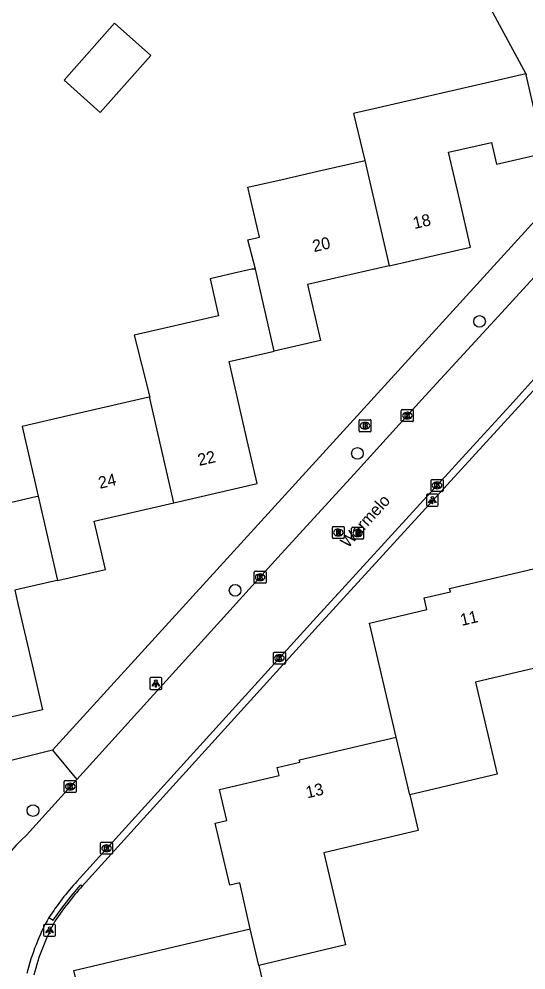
# Model space of a CAD drawing. Extents: x 157663 to 158496, y 379212 to 380934.
# Drawn here: x 158156.2 to 158198.6, y 380518.3 to 380597.8 of the extents above; entities that cross this region are included whole.
import ezdxf

# ---------------------------------------------------------------- set-up
doc = ezdxf.new("R2010")
doc.units = 0
for name, color, linetype in [('IMGEO_Boom', 7, 'Continuous'), ('IMGEO_Brandkraan', 7, 'Continuous'), ('IMGEO_Groenvoorziening', 7, 'Continuous'), ('IMGEO_Kolk', 7, 'Continuous'), ('IMGEO_Lichtpunt', 7, 'Continuous'), ('IMGEO_Openbare_ruimte_label', 7, 'Continuous'), ('IMGEO_Pand', 7, 'Continuous'), ('IMGEO_Pand_nummerreeks', 7, 'Continuous'), ('IMGEO_Rijbaan_lokaal_open', 7, 'Continuous'), ('IMGEO_Rioolput', 7, 'Continuous'), ('IMGEO_Voetpad_open', 7, 'Continuous')]:
    doc.layers.add(name, color=color, linetype=linetype)

msp = doc.modelspace()

# ---------------------------------------------------------------- linework, layer by layer
at = {"layer": 'IMGEO_Boom'}
for centre in [(158194.698, 380572.534), (158184.483, 380561.502), (158174.25, 380550.048), (158157.337, 380531.639)]:
    msp.add_circle(centre, 0.489, dxfattribs=at)
at = {"layer": 'IMGEO_Brandkraan'}
for p, q in [((158184.616, 380563.393), (158184.616, 380564.245)), ((158184.691, 380564.319), (158185.543, 380564.319)), ((158185.104, 380564.099), (158185.129, 380564.099)), ((158185.617, 380564.245), (158185.617, 380563.393)), ((158185.543, 380563.319), (158184.691, 380563.319)), ((158185.127, 380563.539), (158185.102, 380563.539))]:
    msp.add_line(p, q, dxfattribs=at)
for points in [[(158184.616, 380563.393), (158184.616, 380564.245)], [(158184.691, 380564.319), (158185.543, 380564.319)], [(158184.964, 380564.019), (158184.964, 380563.619), (158185.177, 380563.619)], [(158185.195, 380564.019), (158184.964, 380564.019)], [(158185.143, 380563.938), (158185.089, 380563.938), (158185.089, 380563.862)], [(158185.089, 380563.862), (158185.142, 380563.862)], [(158185.151, 380563.786), (158185.089, 380563.786), (158185.089, 380563.705)], [(158185.089, 380563.705), (158185.151, 380563.705)], [(158185.617, 380564.245), (158185.617, 380563.393)], [(158185.543, 380563.319), (158184.691, 380563.319)]]:
    msp.add_lwpolyline(points, dxfattribs=at)
for centre, radius, start, end in [((158184.693, 380564.243), 0.0765, 91.55205, 178.44795), ((158184.693, 380564.243), 0.0765, 91.55205, 178.44795), ((158185.144, 380563.9), 0.0379, 267.82845, 90.93552), ((158185.152, 380563.745), 0.0404, 269.87594, 90.50774), ((158185.183, 380563.87), 0.251, 268.66757, 293.53466), ((158185.199, 380563.874), 0.145, 59.4692, 91.53667), ((158185.224, 380563.921), 0.0922, 285.51372, 58.15012), ((158185.229, 380563.729), 0.105, 301.31148, 78.98903), ((158185.541, 380564.243), 0.0765, 1.55205, 88.44795), ((158185.541, 380564.243), 0.0765, 1.55205, 88.44795), ((158184.693, 380563.395), 0.0765, 181.55205, 268.44795), ((158184.693, 380563.395), 0.0765, 181.55205, 268.44795), ((158185.541, 380563.395), 0.0765, 271.55205, 358.44795), ((158185.541, 380563.395), 0.0765, 271.55205, 358.44795)]:
    msp.add_arc(centre, radius, start, end, dxfattribs=at)
for centre, major_axis, ratio, start_param, end_param in [((158185.103, 380563.819), (-0.387, 0.002), 0.722429, 4.712389, 7.853982), ((158185.128, 380563.819), (-0.39, 0.002), 0.717154, 1.570796, 4.712389)]:
    msp.add_ellipse(centre, major_axis=major_axis, ratio=ratio, start_param=start_param, end_param=end_param, dxfattribs=at)
at = {"layer": 'IMGEO_Groenvoorziening'}
msp.add_lwpolyline([(158173.501, 380635.134), (158174.629, 380630.369), (158177.674, 380619.056), (158182.988, 380612.841), (158191.552, 380606.256), (158198.57, 380593.237)], dxfattribs=at)
at = {"layer": 'IMGEO_Kolk'}
for p, q in [((158188.155, 380564.235), (158188.155, 380565.087)), ((158188.23, 380565.161), (158189.082, 380565.161)), ((158188.643, 380564.941), (158188.668, 380564.941)), ((158189.156, 380565.087), (158189.156, 380564.235)), ((158189.082, 380564.161), (158188.23, 380564.161)), ((158188.666, 380564.381), (158188.641, 380564.381)), ((158190.647, 380558.4), (158190.647, 380559.252)), ((158190.722, 380559.326), (158191.574, 380559.326)), ((158191.135, 380559.106), (158191.16, 380559.106)), ((158191.648, 380559.252), (158191.648, 380558.4)), ((158191.574, 380558.326), (158190.722, 380558.326)), ((158191.158, 380558.546), (158191.133, 380558.546)), ((158175.84, 380550.718), (158175.84, 380551.57)), ((158175.915, 380551.644), (158176.767, 380551.644)), ((158176.328, 380551.424), (158176.353, 380551.424)), ((158176.841, 380551.57), (158176.841, 380550.718)), ((158176.767, 380550.644), (158175.915, 380550.644)), ((158176.351, 380550.864), (158176.326, 380550.864)), ((158177.451, 380543.961), (158177.451, 380544.813)), ((158177.526, 380544.887), (158178.378, 380544.887)), ((158177.939, 380544.667), (158177.964, 380544.667)), ((158178.452, 380544.813), (158178.452, 380543.961)), ((158178.378, 380543.887), (158177.526, 380543.887)), ((158177.962, 380544.107), (158177.937, 380544.107)), ((158159.952, 380533.215), (158159.952, 380534.067)), ((158160.027, 380534.141), (158160.879, 380534.141)), ((158160.44, 380533.921), (158160.465, 380533.921)), ((158160.953, 380534.067), (158160.953, 380533.215)), ((158160.879, 380533.141), (158160.027, 380533.141)), ((158160.463, 380533.361), (158160.438, 380533.361)), ((158162.993, 380528.058), (158162.993, 380528.91)), ((158163.068, 380528.984), (158163.92, 380528.984)), ((158163.481, 380528.764), (158163.506, 380528.764)), ((158163.994, 380528.91), (158163.994, 380528.058)), ((158163.92, 380527.984), (158163.068, 380527.984)), ((158163.504, 380528.204), (158163.479, 380528.204))]:
    msp.add_line(p, q, dxfattribs=at)
for points in [[(158188.155, 380564.235), (158188.155, 380565.087)], [(158188.23, 380565.161), (158189.082, 380565.161)], [(158188.476, 380564.861), (158188.599, 380564.861), (158188.599, 380564.71), (158188.729, 380564.861), (158188.893, 380564.861), (158188.747, 380564.71), (158188.9, 380564.461), (158188.748, 380564.461), (158188.663, 380564.625), (158188.599, 380564.558), (158188.599, 380564.461), (158188.476, 380564.461), (158188.476, 380564.861)], [(158189.156, 380565.087), (158189.156, 380564.235)], [(158189.082, 380564.161), (158188.23, 380564.161)], [(158190.647, 380558.4), (158190.647, 380559.252)], [(158190.722, 380559.326), (158191.574, 380559.326)], [(158190.968, 380559.026), (158191.091, 380559.026), (158191.091, 380558.875), (158191.221, 380559.026), (158191.385, 380559.026), (158191.239, 380558.875), (158191.392, 380558.626), (158191.24, 380558.626), (158191.155, 380558.79), (158191.091, 380558.723), (158191.091, 380558.626), (158190.968, 380558.626), (158190.968, 380559.026)], [(158191.648, 380559.252), (158191.648, 380558.4)], [(158191.574, 380558.326), (158190.722, 380558.326)], [(158175.84, 380550.718), (158175.84, 380551.57)], [(158175.915, 380551.644), (158176.767, 380551.644)], [(158176.161, 380551.344), (158176.284, 380551.344), (158176.284, 380551.193), (158176.414, 380551.344), (158176.578, 380551.344), (158176.432, 380551.193), (158176.585, 380550.944), (158176.433, 380550.944), (158176.348, 380551.108), (158176.284, 380551.041), (158176.284, 380550.944), (158176.161, 380550.944), (158176.161, 380551.344)], [(158176.841, 380551.57), (158176.841, 380550.718)], [(158176.767, 380550.644), (158175.915, 380550.644)], [(158177.451, 380543.961), (158177.451, 380544.813)], [(158177.526, 380544.887), (158178.378, 380544.887)], [(158177.772, 380544.587), (158177.895, 380544.587), (158177.895, 380544.436), (158178.025, 380544.587), (158178.189, 380544.587), (158178.043, 380544.436), (158178.196, 380544.187), (158178.044, 380544.187), (158177.959, 380544.351), (158177.895, 380544.284), (158177.895, 380544.187), (158177.772, 380544.187), (158177.772, 380544.587)], [(158178.452, 380544.813), (158178.452, 380543.961)], [(158178.378, 380543.887), (158177.526, 380543.887)], [(158159.952, 380533.215), (158159.952, 380534.067)], [(158160.027, 380534.141), (158160.879, 380534.141)], [(158160.273, 380533.841), (158160.396, 380533.841), (158160.396, 380533.69), (158160.526, 380533.841), (158160.69, 380533.841), (158160.544, 380533.69), (158160.697, 380533.441), (158160.545, 380533.441), (158160.46, 380533.605), (158160.396, 380533.538), (158160.396, 380533.441), (158160.273, 380533.441), (158160.273, 380533.841)], [(158160.953, 380534.067), (158160.953, 380533.215)], [(158160.879, 380533.141), (158160.027, 380533.141)], [(158162.993, 380528.058), (158162.993, 380528.91)], [(158163.068, 380528.984), (158163.92, 380528.984)], [(158163.314, 380528.684), (158163.437, 380528.684), (158163.437, 380528.533), (158163.567, 380528.684), (158163.731, 380528.684), (158163.585, 380528.533), (158163.738, 380528.284), (158163.586, 380528.284), (158163.501, 380528.448), (158163.437, 380528.381), (158163.437, 380528.284), (158163.314, 380528.284), (158163.314, 380528.684)], [(158163.994, 380528.91), (158163.994, 380528.058)], [(158163.92, 380527.984), (158163.068, 380527.984)]]:
    msp.add_lwpolyline(points, dxfattribs=at)
for centre, start, end in [((158188.232, 380565.085), 91.55205, 178.44795), ((158188.232, 380565.085), 91.55205, 178.44795), ((158189.08, 380565.085), 1.55205, 88.44795), ((158189.08, 380565.085), 1.55205, 88.44795), ((158188.232, 380564.237), 181.55205, 268.44795), ((158188.232, 380564.237), 181.55205, 268.44795), ((158189.08, 380564.237), 271.55205, 358.44795), ((158189.08, 380564.237), 271.55205, 358.44795), ((158190.724, 380559.25), 91.55205, 178.44795), ((158190.724, 380559.25), 91.55205, 178.44795), ((158191.572, 380559.25), 1.55205, 88.44795), ((158191.572, 380559.25), 1.55205, 88.44795), ((158190.724, 380558.402), 181.55205, 268.44795), ((158190.724, 380558.402), 181.55205, 268.44795), ((158191.572, 380558.402), 271.55205, 358.44795), ((158191.572, 380558.402), 271.55205, 358.44795), ((158175.917, 380551.568), 91.55205, 178.44795), ((158175.917, 380551.568), 91.55205, 178.44795), ((158176.765, 380551.568), 1.55205, 88.44795), ((158176.765, 380551.568), 1.55205, 88.44795), ((158175.917, 380550.72), 181.55205, 268.44795), ((158175.917, 380550.72), 181.55205, 268.44795), ((158176.765, 380550.72), 271.55205, 358.44795), ((158176.765, 380550.72), 271.55205, 358.44795), ((158177.528, 380544.811), 91.55205, 178.44795), ((158177.528, 380544.811), 91.55205, 178.44795), ((158178.376, 380544.811), 1.55205, 88.44795), ((158178.376, 380544.811), 1.55205, 88.44795), ((158177.528, 380543.963), 181.55205, 268.44795), ((158177.528, 380543.963), 181.55205, 268.44795), ((158178.376, 380543.963), 271.55205, 358.44795), ((158178.376, 380543.963), 271.55205, 358.44795), ((158160.029, 380534.065), 91.55205, 178.44795), ((158160.029, 380534.065), 91.55205, 178.44795), ((158160.877, 380534.065), 1.55205, 88.44795), ((158160.877, 380534.065), 1.55205, 88.44795), ((158160.029, 380533.217), 181.55205, 268.44795), ((158160.029, 380533.217), 181.55205, 268.44795), ((158160.877, 380533.217), 271.55205, 358.44795), ((158160.877, 380533.217), 271.55205, 358.44795), ((158163.07, 380528.908), 91.55205, 178.44795), ((158163.07, 380528.908), 91.55205, 178.44795), ((158163.918, 380528.908), 1.55205, 88.44795), ((158163.918, 380528.908), 1.55205, 88.44795), ((158163.07, 380528.06), 181.55205, 268.44795), ((158163.07, 380528.06), 181.55205, 268.44795), ((158163.918, 380528.06), 271.55205, 358.44795), ((158163.918, 380528.06), 271.55205, 358.44795)]:
    msp.add_arc(centre, 0.0765, start, end, dxfattribs=at)
for centre, major_axis, ratio, start_param, end_param in [((158188.642, 380564.661), (-0.387, 0.002), 0.722429, 4.712389, 7.853982), ((158188.667, 380564.661), (-0.39, 0.002), 0.717154, 1.570796, 4.712389), ((158191.134, 380558.826), (-0.387, 0.002), 0.722429, 4.712389, 7.853982), ((158191.159, 380558.826), (-0.39, 0.002), 0.717154, 1.570796, 4.712389), ((158176.327, 380551.144), (-0.387, 0.002), 0.722429, 4.712389, 7.853982), ((158176.352, 380551.144), (-0.39, 0.002), 0.717154, 1.570796, 4.712389), ((158177.938, 380544.387), (-0.387, 0.002), 0.722429, 4.712389, 7.853982), ((158177.963, 380544.387), (-0.39, 0.002), 0.717154, 1.570796, 4.712389), ((158160.439, 380533.641), (-0.387, 0.002), 0.722429, 4.712389, 7.853982), ((158160.464, 380533.641), (-0.39, 0.002), 0.717154, 1.570796, 4.712389), ((158163.48, 380528.484), (-0.387, 0.002), 0.722429, 4.712389, 7.853982), ((158163.505, 380528.484), (-0.39, 0.002), 0.717154, 1.570796, 4.712389)]:
    msp.add_ellipse(centre, major_axis=major_axis, ratio=ratio, start_param=start_param, end_param=end_param, dxfattribs=at)
at = {"layer": 'IMGEO_Lichtpunt'}
for p, q in [((158191.154, 380558.089), (158190.346, 380558.089)), ((158191.154, 380558.089), (158190.346, 380558.089)), ((158190.252, 380557.994), (158190.252, 380557.187)), ((158190.252, 380557.994), (158190.252, 380557.187)), ((158191.248, 380557.187), (158191.248, 380557.994)), ((158191.248, 380557.187), (158191.248, 380557.994)), ((158190.346, 380557.093), (158191.154, 380557.093)), ((158190.346, 380557.093), (158191.154, 380557.093)), ((158167.115, 380542.671), (158167.115, 380541.864)), ((158167.115, 380542.671), (158167.115, 380541.864)), ((158168.017, 380542.766), (158167.209, 380542.766)), ((158168.017, 380542.766), (158167.209, 380542.766)), ((158168.111, 380541.864), (158168.111, 380542.671)), ((158168.111, 380541.864), (158168.111, 380542.671)), ((158167.209, 380541.77), (158168.017, 380541.77)), ((158167.209, 380541.77), (158168.017, 380541.77)), ((158158.223, 380522.027), (158158.223, 380521.22)), ((158158.223, 380522.027), (158158.223, 380521.22)), ((158159.125, 380522.122), (158158.317, 380522.122)), ((158159.125, 380522.122), (158158.317, 380522.122)), ((158159.219, 380521.22), (158159.219, 380522.027)), ((158159.219, 380521.22), (158159.219, 380522.027)), ((158158.317, 380521.126), (158159.125, 380521.126)), ((158158.317, 380521.126), (158159.125, 380521.126))]:
    msp.add_line(p, q, dxfattribs=at)
for points in [[(158190.626, 380557.658), (158190.665, 380557.63), (158190.477, 380557.368), (158190.439, 380557.395), (158190.626, 380557.658)], [(158190.728, 380557.61), (158190.775, 380557.61), (158190.775, 380557.288), (158190.728, 380557.288), (158190.728, 380557.61)], [(158190.838, 380557.63), (158190.876, 380557.657), (158191.063, 380557.395), (158191.024, 380557.367), (158190.838, 380557.63)], [(158167.489, 380542.335), (158167.528, 380542.307), (158167.34, 380542.045), (158167.302, 380542.072), (158167.489, 380542.335)], [(158167.591, 380542.287), (158167.638, 380542.287), (158167.638, 380541.965), (158167.591, 380541.965), (158167.591, 380542.287)], [(158167.701, 380542.307), (158167.739, 380542.334), (158167.926, 380542.072), (158167.887, 380542.044), (158167.701, 380542.307)], [(158158.597, 380521.691), (158158.636, 380521.663), (158158.448, 380521.401), (158158.41, 380521.428), (158158.597, 380521.691)], [(158158.699, 380521.643), (158158.746, 380521.643), (158158.746, 380521.321), (158158.699, 380521.321), (158158.699, 380521.643)], [(158158.809, 380521.663), (158158.847, 380521.69), (158159.034, 380521.428), (158158.995, 380521.4), (158158.809, 380521.663)]]:
    msp.add_lwpolyline(points, dxfattribs=at)
for centre in [(158190.751, 380557.792), (158167.614, 380542.469), (158158.722, 380521.825)]:
    msp.add_circle(centre, 0.0994, dxfattribs=at)
for centre, start, end in [((158190.346, 380557.994), 90, 180), ((158190.346, 380557.994), 90, 180), ((158191.154, 380557.994), 0, 90), ((158191.154, 380557.994), 0, 90), ((158190.346, 380557.187), 180, 270), ((158190.346, 380557.187), 180, 270), ((158191.154, 380557.187), 270, 0), ((158191.154, 380557.187), 270, 360), ((158167.209, 380542.671), 90, 180), ((158167.209, 380542.671), 90, 180), ((158168.017, 380542.671), 0, 90), ((158168.017, 380542.671), 0, 90), ((158167.209, 380541.864), 180, 270), ((158167.209, 380541.864), 180, 270), ((158168.017, 380541.864), 270, 0), ((158168.017, 380541.864), 270, 360), ((158158.317, 380522.027), 90, 180), ((158158.317, 380522.027), 90, 180), ((158159.125, 380522.027), 0, 90), ((158159.125, 380522.027), 0, 90), ((158158.317, 380521.22), 180, 270), ((158158.317, 380521.22), 180, 270), ((158159.125, 380521.22), 270, 0), ((158159.125, 380521.22), 270, 360)]:
    msp.add_arc(centre, 0.0946, start, end, dxfattribs=at)
at = {"layer": 'IMGEO_Pand'}
for points in [[(158162.964, 380590.019), (158159.934, 380592.701), (158164.152, 380597.466), (158167.182, 380594.783), (158162.964, 380590.019)], [(158198.57, 380593.237), (158194.846, 380592.382), (158189.973, 380591.263), (158184.16, 380589.927), (158185.1, 380585.999)], [(158187.126, 380577.186), (158193.933, 380578.75), (158193.149, 380582.163), (158192.11, 380586.684), (158195.708, 380587.511), (158196.124, 380585.698), (158196.369, 380585.754), (158197.821, 380586.087), (158200.115, 380586.615), (158198.612, 380593.159)], [(158198.57, 380593.237), (158198.593, 380593.242), (158198.612, 380593.159)], [(158175.941, 380576.918), (158175.325, 380579.351), (158176.275, 380579.569), (158175.313, 380583.75), (158178.174, 380584.408), (158181.524, 380585.177), (158184.874, 380585.947), (158185.1, 380585.999)], [(158185.1, 380585.999), (158187.126, 380577.186)], [(158187.126, 380577.186), (158180.315, 380575.621), (158181.391, 380570.941), (158177.519, 380570.052)], [(158175.941, 380576.918), (158175.645, 380576.903), (158174.173, 380576.565), (158172.155, 380576.101), (158172.868, 380573.001), (158165.805, 380571.378), (158167.099, 380566.215)], [(158177.519, 380570.052), (158175.941, 380576.918)], [(158169.132, 380557.378), (158176.091, 380558.977), (158175.261, 380562.59), (158173.745, 380569.185), (158175.579, 380569.606), (158177.413, 380570.027), (158177.519, 380570.052)], [(158167.099, 380566.215), (158166.906, 380566.171), (158164.383, 380565.591), (158160.255, 380564.643), (158156.419, 380563.761), (158157.76, 380557.928)], [(158169.132, 380557.378), (158167.124, 380566.117), (158167.099, 380566.215)], [(158148.947, 380547.167), (158148.157, 380550.608), (158155.319, 380552.251), (158154.202, 380557.11), (158155.893, 380557.499), (158157.584, 380557.887), (158157.76, 380557.928)], [(158157.76, 380557.928), (158159.381, 380550.88)], [(158159.381, 380550.88), (158163.395, 380551.801), (158162.465, 380555.846), (158169.132, 380557.378)], [(158187.735, 380537.778), (158185.487, 380547.312), (158190.285, 380548.444), (158190.055, 380549.42), (158192.256, 380549.939), (158192.195, 380550.201), (158200.521, 380552.165), (158201.669, 380547.299), (158202.127, 380545.357)], [(158159.381, 380550.88), (158159.224, 380550.844), (158156.65, 380550.252), (158155.822, 380550.062), (158156.109, 380548.813), (158157.253, 380543.835), (158158.12, 380540.062), (158150.955, 380538.416)], [(158202.281, 380544.235), (158194.371, 380542.37), (158196.187, 380534.669), (158188.862, 380532.941)], [(158175.513, 380521.752), (158174.643, 380525.592), (158173.811, 380525.395), (158172.585, 380530.592), (158173.552, 380530.82), (158172.945, 380533.393), (158177.922, 380534.567), (158177.762, 380535.245), (158179.67, 380535.695), (158179.63, 380535.867), (158187.735, 380537.778)], [(158188.862, 380532.941), (158187.735, 380537.778)], [(158188.862, 380532.941), (158189.564, 380529.963), (158181.663, 380528.1), (158183.479, 380520.4), (158176.232, 380518.691)], [(158163.742, 380503.42), (158163.028, 380506.456), (158162.778, 380506.397), (158161.618, 380511.317), (158161.82, 380511.364), (158161.36, 380513.312), (158161.89, 380513.437), (158160.75, 380518.271), (158170.055, 380520.465), (158175.513, 380521.752)], [(158176.232, 380518.691), (158175.513, 380521.752)], [(158176.232, 380518.691), (158177.114, 380514.813), (158177.423, 380513.454), (158173.752, 380512.588), (158173.432, 380513.944), (158169.75, 380513.076), (158171.592, 380505.268)]]:
    msp.add_lwpolyline(points, dxfattribs=at)
at = {"layer": 'IMGEO_Rijbaan_lokaal_open'}
for points in [[(158161.006, 380534.247), (158166.087, 380539.848), (158177.834, 380552.801), (158184.482, 380560.078), (158187.705, 380563.61), (158190.145, 380566.306), (158196.246, 380572.942), (158201.362, 380578.522), (158204.43, 380581.784)], [(158161.015, 380525.72), (158180.789, 380547.505), (158184.386, 380551.425), (158194.162, 380562.139), (158197.241, 380565.485), (158199.255, 380567.716), (158202.84, 380571.622), (158208.577, 380577.884)], [(158161.006, 380534.247), (158156.78, 380529.591)]]:
    msp.add_lwpolyline(points, dxfattribs=at)
for centre, radius, start, end in [((158168.779, 380516.794), 17.542, 133.15655, 164.30038), ((158178.257, 380509.874), 23.417, 137.41664, 146.79665), ((158175.094, 380513.561), 18.801, 150.92098, 166.30089)]:
    msp.add_arc(centre, radius, start, end, dxfattribs=at)
at = {"layer": 'IMGEO_Rioolput'}
for p, q in [((158182.383, 380554.457), (158182.383, 380555.309)), ((158182.458, 380555.383), (158183.31, 380555.383)), ((158182.871, 380555.163), (158182.896, 380555.163)), ((158183.384, 380555.309), (158183.384, 380554.457)), ((158183.999, 380554.41), (158183.999, 380555.262)), ((158184.074, 380555.336), (158184.926, 380555.336)), ((158184.487, 380555.116), (158184.512, 380555.116)), ((158185, 380555.262), (158185, 380554.41)), ((158183.31, 380554.383), (158182.458, 380554.383)), ((158182.894, 380554.603), (158182.869, 380554.603)), ((158184.926, 380554.336), (158184.074, 380554.336)), ((158184.51, 380554.556), (158184.485, 380554.556))]:
    msp.add_line(p, q, dxfattribs=at)
for points in [[(158182.383, 380554.457), (158182.383, 380555.309)], [(158182.458, 380555.383), (158183.31, 380555.383)], [(158182.972, 380555.081), (158182.72, 380555.083), (158182.72, 380554.683)], [(158182.898, 380555.002), (158182.844, 380555.002), (158182.844, 380554.921)], [(158182.844, 380554.921), (158182.896, 380554.921)], [(158183.384, 380555.309), (158183.384, 380554.457)], [(158183.999, 380554.41), (158183.999, 380555.262)], [(158184.074, 380555.336), (158184.926, 380555.336)], [(158184.588, 380555.034), (158184.336, 380555.036), (158184.336, 380554.636)], [(158184.514, 380554.955), (158184.46, 380554.955), (158184.46, 380554.874)], [(158185, 380555.262), (158185, 380554.41)], [(158183.31, 380554.383), (158182.458, 380554.383)], [(158182.72, 380554.683), (158182.844, 380554.683), (158182.844, 380554.845), (158182.855, 380554.845)], [(158182.902, 380554.816), (158182.973, 380554.683), (158183.113, 380554.683), (158183.048, 380554.809)], [(158184.926, 380554.336), (158184.074, 380554.336)], [(158184.336, 380554.636), (158184.46, 380554.636), (158184.46, 380554.798), (158184.471, 380554.798)], [(158184.46, 380554.874), (158184.512, 380554.874)], [(158184.518, 380554.769), (158184.589, 380554.636), (158184.729, 380554.636), (158184.664, 380554.762)]]:
    msp.add_lwpolyline(points, dxfattribs=at)
for centre, radius, start, end in [((158182.46, 380555.307), 0.0765, 91.55205, 178.44795), ((158182.46, 380555.307), 0.0765, 91.55205, 178.44795), ((158182.88, 380555.11), 0.19, 274.7715, 282.96867), ((158182.904, 380554.906), 0.0964, 77.00612, 93.18647), ((158182.918, 380554.963), 0.0378, 276.66336, 79.67722), ((158182.971, 380554.971), 0.109, 350.36119, 89.41601), ((158182.969, 380554.971), 0.112, 277.58423, 350.98172), ((158183.308, 380555.307), 0.0765, 1.55205, 88.44795), ((158183.308, 380555.307), 0.0765, 1.55205, 88.44795), ((158184.076, 380555.26), 0.0765, 91.55205, 178.44795), ((158184.076, 380555.26), 0.0765, 91.55205, 178.44795), ((158184.52, 380554.859), 0.0964, 77.00612, 93.18647), ((158184.534, 380554.916), 0.0378, 276.66336, 79.67722), ((158184.587, 380554.924), 0.109, 350.36119, 89.41601), ((158184.585, 380554.924), 0.112, 277.58423, 350.98172), ((158184.924, 380555.26), 0.0765, 1.55205, 88.44795), ((158184.924, 380555.26), 0.0765, 1.55205, 88.44795), ((158182.46, 380554.459), 0.0765, 181.55205, 268.44795), ((158182.46, 380554.459), 0.0765, 181.55205, 268.44795), ((158182.854, 380554.792), 0.0533, 26.02933, 88.69889), ((158182.953, 380554.756), 0.108, 29.51342, 73.79051), ((158183.308, 380554.459), 0.0765, 271.55205, 358.44795), ((158183.308, 380554.459), 0.0765, 271.55205, 358.44795), ((158184.076, 380554.412), 0.0765, 181.55205, 268.44795), ((158184.076, 380554.412), 0.0765, 181.55205, 268.44795), ((158184.47, 380554.745), 0.0533, 26.02933, 88.69889), ((158184.496, 380555.063), 0.19, 274.7715, 282.96867), ((158184.569, 380554.709), 0.108, 29.51342, 73.79051), ((158184.924, 380554.412), 0.0765, 271.55205, 358.44795), ((158184.924, 380554.412), 0.0765, 271.55205, 358.44795)]:
    msp.add_arc(centre, radius, start, end, dxfattribs=at)
for centre, major_axis, ratio, start_param, end_param in [((158182.87, 380554.883), (-0.387, 0.002), 0.722429, 4.712389, 7.853982), ((158182.895, 380554.883), (-0.39, 0.002), 0.717154, 1.570796, 4.712389), ((158184.486, 380554.836), (-0.387, 0.002), 0.722429, 4.712389, 7.853982), ((158184.511, 380554.836), (-0.39, 0.002), 0.717154, 1.570796, 4.712389)]:
    msp.add_ellipse(centre, major_axis=major_axis, ratio=ratio, start_param=start_param, end_param=end_param, dxfattribs=at)
at = {"layer": 'IMGEO_Voetpad_open'}
for points in [[(158203.054, 380585.037), (158158.961, 380536.699)], [(158206.036, 380574.234), (158181.237, 380547.104), (158161.46, 380525.323)], [(158158.961, 380536.699), (158152.052, 380534.953)], [(158158.961, 380536.699), (158161.006, 380534.247)], [(158158.663, 380522.698), (158159.032, 380522.468), (158159.759, 380523.488), (158160.529, 380524.476), (158161.341, 380525.43), (158161.46, 380525.323)], [(158161.46, 380525.323), (158161.459, 380525.322)]]:
    msp.add_lwpolyline(points, dxfattribs=at)
for centre, radius, start, end in [((158134.16, 380565.326), 73.859, 24.73125, 31.74923), ((158182.325, 380506.662), 27.992, 138.19448, 145.81791), ((158175.74, 380513.344), 18.88, 151.37387, 166.08831)]:
    msp.add_arc(centre, radius, start, end, dxfattribs=at)

# ---------------------------------------------------------------- texts
at = {"layer": 'IMGEO_Openbare_ruimte_label'}
msp.add_text('Warmelo', height=1, rotation=47.71475, dxfattribs=at).set_placement((158183.694, 380553.531))
at = {"layer": 'IMGEO_Pand_nummerreeks'}
for s, rotation, p in [('18', 12.93739, (158189.251, 380580.259)), ('20', 12.93739, (158180.844, 380578.328)), ('22', 12.94312, (158171.239, 380560.448)), ('24', 12.94312, (158162.932, 380558.538)), ('11', 13.27274, (158193.207, 380547.07)), ('13', 13.26692, (158180.285, 380532.652))]:
    msp.add_text(s, height=1, rotation=rotation, dxfattribs=at).set_placement(p)

doc.saveas('drawing.dxf')
